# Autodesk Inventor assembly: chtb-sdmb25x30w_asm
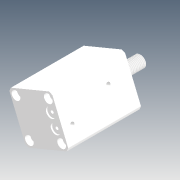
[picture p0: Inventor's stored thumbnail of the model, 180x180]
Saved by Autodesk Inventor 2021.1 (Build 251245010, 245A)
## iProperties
Company: Microsoft
Created: 2018-05
Part Number: chtb-sdmb25x30w_asm
Description: STEP AP214
Document SubType Name: Assembly
Designer: user
Title: chtb-sdmb25x30w_asm.STEP
Author: Windows
Revision Number: ÈÎºÎ
Sending System: SolidWorks 2015
Preprocessor: SwSTEP 2.0
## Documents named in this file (4)
- D:\Vault_2016\Projekty\Clamptek\Hydraulic\CHTB\CHTB-25\Inventor\chtb-sdmb25x30w\chtb-sdmb25x30w_asm.iam
- D:\Vault_2016\Projekty\Clamptek\Hydraulic\CHTB\CHTB-25\Inventor\chtb-sdmb25x30w\CHTB-25QG.ipt
- D:\Vault_2016\Projekty\Clamptek\Hydraulic\CHTB\CHTB-25\Inventor\chtb-sdmb25x30w\CHTB-SDMB25X30NBT.ipt
- D:\Vault_2016\Projekty\Clamptek\Hydraulic\CHTB\CHTB-25\Inventor\chtb-sdmb25x30w\CHTB-SDMB25X30WHSG.ipt
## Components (3 placed, 3 different names)
1. CHTB-25QG_1
2. CHTB-SDMB25X30NBT_2
3. CHTB-SDMB25X30WHSG_3
